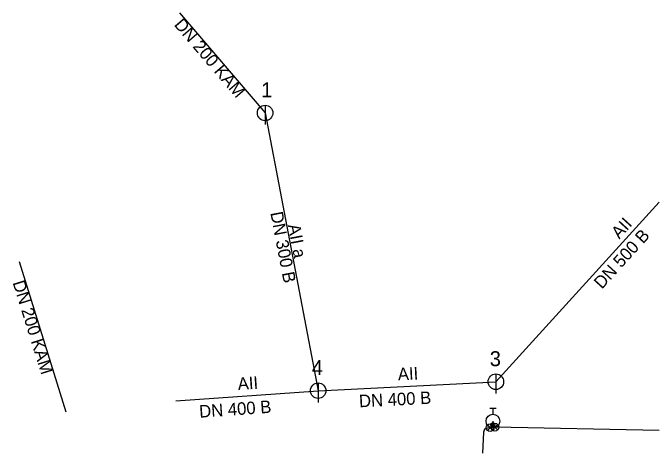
# Model space of a CAD drawing. Extents: x -456606 to -456522.9, y -1112345.2 to -1112288.6.
import ezdxf

# ---------------------------------------------------------------- set-up
doc = ezdxf.new("R2010")
doc.units = 0
for name, color, linetype in [('_pripojka_kanal_jednotna_priblizne_', 7, 'Continuous'), ('_stoka_jednotna_smvak_prevzato_z_dokumentace_', 7, 'Continuous'), ('_tlakova_stoka_jednotna_smvak_prevzato_z_dokumentace_', 7, 'Continuous'), ('Default', 7, 'Continuous'), ('MoLevel 119', 7, 'Continuous'), ('MoLevel 120', 7, 'Continuous'), ('MoLevel 124', 7, 'Continuous'), ('MoLevel 61', 7, 'Continuous'), ('MoLevel 62', 7, 'Continuous'), ('MoLevel 68', 7, 'Continuous'), ('MoLevel 69', 7, 'Continuous')]:
    doc.layers.add(name, color=color, linetype=linetype)

# ---------------------------------------------------------------- blocks, each defined once
blk = doc.blocks.new('_hydrant_kanal_')
at = {"layer": 'Default'}
for p, q in [((-0.0000225, 0.000095), (0.0000225, 0.000095)), ((0, 0.000095), (0, 0.00005))]:
    blk.add_line(p, q, dxfattribs=at)
blk.add_circle((0, 0), 0.00005, dxfattribs=at)
blk = doc.blocks.new('_sachta_kanal_prevzato_z_dokumentace_')
at = {"layer": 'Default'}
blk.add_line((0, 0.00005), (0, -0.000075), dxfattribs=at)
blk.add_circle((0, 0), 0.00005, dxfattribs=at)
blk = doc.blocks.new('_uzaver_kanal_')
at = {"layer": 'Default'}
for p, q in [((-0.000035, -0.000035), (0.000035, 0.000035)), ((0.000035, -0.000035), (-0.000035, 0.000035))]:
    blk.add_line(p, q, dxfattribs=at)
for radius in [0.00005, 0.0000025]:
    blk.add_circle((0, 0), radius, dxfattribs=at)

msp = doc.modelspace()

# ---------------------------------------------------------------- linework, layer by layer
at = {"layer": '_pripojka_kanal_jednotna_priblizne_'}
for p, q in [((-456584.589, -1112288.636), (-456573.58, -1112301.5)), ((-456605.253, -1112320.617), (-456599.23, -1112339.94))]:
    msp.add_line(p, q, dxfattribs=at)
at = {"layer": '_stoka_jednotna_smvak_prevzato_z_dokumentace_'}
for p, q in [((-456573.58, -1112301.5), (-456566.75, -1112337.22)), ((-456543.88, -1112336.07), (-456522.869, -1112312.958)), ((-456566.75, -1112337.22), (-456543.88, -1112336.07)), ((-456585.07, -1112338.51), (-456566.75, -1112337.22))]:
    msp.add_line(p, q, dxfattribs=at)
at = {"layer": '_tlakova_stoka_jednotna_smvak_prevzato_z_dokumentace_'}
for points in [[(-456544.25, -1112341.14), (-456544.28, -1112341.6), (-456544.28, -1112341.937)], [(-456522.869, -1112342.345), (-456544, -1112341.91), (-456544.62, -1112341.97), (-456544.94, -1112342.02), (-456545.33, -1112342.15), (-456545.49, -1112342.54), (-456545.588, -1112345.243)]]:
    msp.add_lwpolyline(points, dxfattribs=at)

# ---------------------------------------------------------------- block references
at = {"layer": 'MoLevel 119', "xscale": 20000, "yscale": 20000}
for p in [(-456573.58, -1112301.5), (-456543.88, -1112336.07), (-456566.75, -1112337.22)]:
    msp.add_blockref('_sachta_kanal_prevzato_z_dokumentace_', p, dxfattribs=at)
at = {"layer": 'MoLevel 61'}
for p, xscale, yscale in [((-456544.62, -1112341.97), 10000, 10000), ((-456544.28, -1112341.6), 5000, 5000), ((-456544, -1112341.91), 10000, 10000)]:
    msp.add_blockref('_uzaver_kanal_', p, dxfattribs=dict(at, xscale=xscale, yscale=yscale))
at = {"layer": 'MoLevel 62', "xscale": 17636.68430335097, "yscale": 17636.68430335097}
msp.add_blockref('_hydrant_kanal_', (-456544.25, -1112341.14), dxfattribs=at)

# ---------------------------------------------------------------- texts
at = {"layer": 'MoLevel 120'}
for s, p in [('1', (-456574.084, -1112299.5)), ('3', (-456544.66, -1112334.07)), ('4', (-456567.575, -1112335.22))]:
    msp.add_text(s, height=1.926, dxfattribs=at).set_placement(p)
at = {"layer": 'MoLevel 124'}
for rotation, p in [(310.55689, (-456585.372, -1112290.189)), (287.31232, (-456606.093, -1112323.314))]:
    msp.add_text('DN 200 KAM', height=1.6049, rotation=rotation, dxfattribs=at).set_placement(p)
at = {"layer": 'MoLevel 68'}
for s, rotation, p in [('DN 300 B', 280.82484, (-456572.911, -1112314.344)), ('DN 500 B', 47.72553, (-456530.227, -1112324.238)), ('DN 400 B', 2.87865, (-456561.455, -1112339.361)), ('DN 400 B', 4.02783, (-456582.011, -1112340.703))]:
    msp.add_text(s, height=1.6049, rotation=rotation, dxfattribs=at).set_placement(p)
at = {"layer": 'MoLevel 69'}
for s, rotation, p in [('AII', 47.72553, (-456527.996, -1112317.798)), ('AII a', 280.82484, (-456570.667, -1112315.933)), ('AII', 2.87865, (-456556.46, -1112335.903)), ('AII', 4.02783, (-456577.054, -1112337.146))]:
    msp.add_text(s, height=1.6049, rotation=rotation, dxfattribs=at).set_placement(p)

doc.saveas('drawing.dxf')
